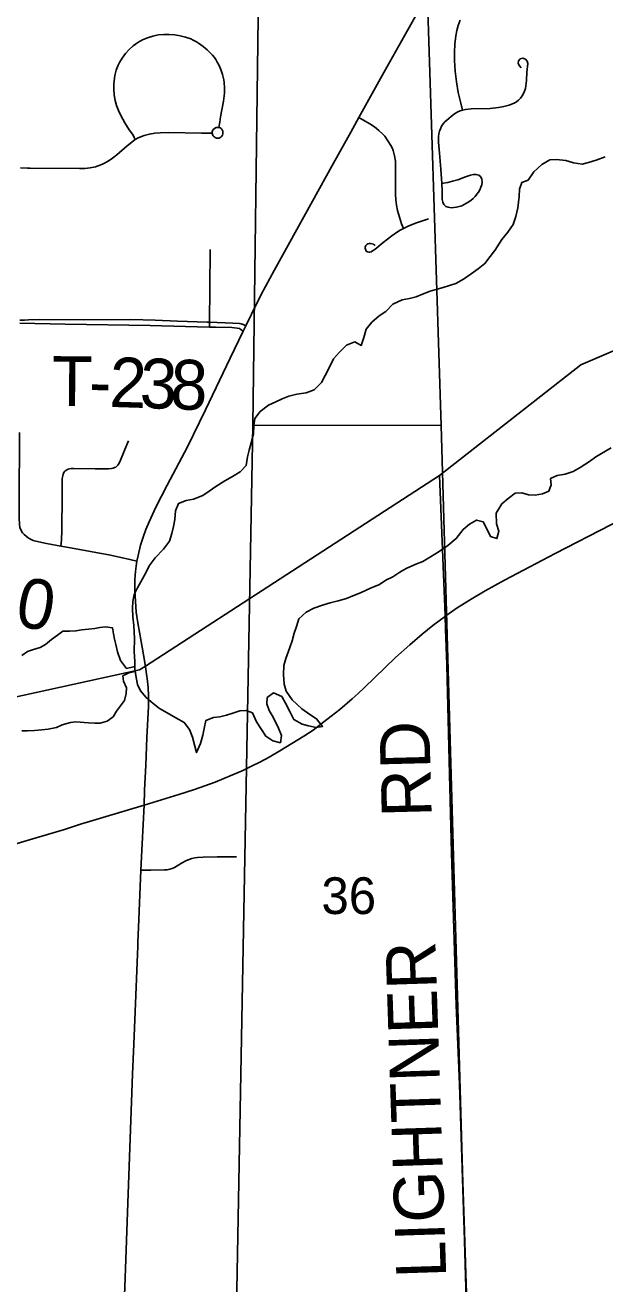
# Model space of a CAD drawing. Extents: x 63.4 to 97.4, y 0.4 to 22.4.
# Drawn here: x 67.452 to 68.112, y 16.594 to 18.029 of the extents above; entities that cross this region are included whole.
import ezdxf

# ---------------------------------------------------------------- set-up
doc = ezdxf.new("R2010")
doc.units = 0
for name, color, linetype in [('GM_X_County_Road', 7, 'Continuous'), ('GM_X_County_Road_Text', 7, 'Continuous'), ('GM_X_Minor_River', 7, 'Continuous'), ('GM_X_Section', 7, 'Continuous'), ('GM_X_Section_Text', 7, 'Continuous'), ('GM_X_State_Route', 7, 'Continuous'), ('GM_X_Township_Road', 7, 'Continuous'), ('GM_X_Township_Road_Text', 7, 'Continuous')]:
    doc.layers.add(name, color=color, linetype=linetype)

msp = doc.modelspace()

# ---------------------------------------------------------------- linework, layer by layer
at = {"layer": 'GM_X_County_Road'}
for points in [[(67.1507, 17.1994), (67.5821, 17.2942), (67.5887, 17.2982), (67.9238, 17.5156), (68.0846, 17.6418), (68.1482, 17.6693)], [(68.1482, 17.6693), (68.0846, 17.6418), (67.9238, 17.5156), (67.9301, 17.356), (67.9306, 17.3404), (67.9319, 17.3001), (67.9354, 17.1603), (67.9374, 17.0857), (67.9399, 16.9987), (67.9427, 16.9118), (67.9463, 16.8217), (67.9514, 16.6664), (67.954, 16.595), (67.9575, 16.4894)], [(67.4926, 17.4352), (67.4761, 17.4383), (67.4639, 17.4409), (67.4609, 17.4418), (67.4579, 17.4431), (67.4551, 17.4447), (67.4528, 17.4464), (67.4508, 17.4484), (67.4487, 17.4505), (67.4473, 17.453), (67.4459, 17.4564), (67.4454, 17.4601), (67.445, 17.4671), (67.4451, 17.4836), (67.4454, 17.5646)], [(67.9575, 16.4894), (67.954, 16.595), (67.9514, 16.6664), (67.9463, 16.8217), (67.9427, 16.9118), (67.9399, 16.9987), (67.9374, 17.0857), (67.9354, 17.1603), (67.9319, 17.3001), (67.9306, 17.3404), (67.9301, 17.356), (67.9238, 17.5156), (67.5887, 17.2982), (67.5821, 17.2942), (67.1507, 17.1994)], [(67.5791, 17.4182), (67.5712, 17.4201), (67.549, 17.425), (67.5035, 17.4332), (67.4926, 17.4352)]]:
    msp.add_lwpolyline(points, dxfattribs=at)
at = {"layer": 'GM_X_Minor_River'}
for points in [[(68.1122, 17.8789), (68.1019, 17.8751), (68.0932, 17.8724), (68.086, 17.8708), (68.0761, 17.8723), (68.0674, 17.8749), (68.0567, 17.876), (68.0492, 17.8756), (68.0401, 17.8702), (68.031, 17.8618), (68.0246, 17.8526), (68.0174, 17.8496), (68.0148, 17.842), (68.0144, 17.834), (68.013, 17.821)], [(68.1122, 17.8789), (68.1019, 17.8751), (68.0932, 17.8724), (68.086, 17.8708), (68.0761, 17.8723), (68.0674, 17.8749), (68.0567, 17.876), (68.0492, 17.8756), (68.0401, 17.8702), (68.031, 17.8618), (68.0246, 17.8526), (68.0174, 17.8496), (68.0148, 17.842), (68.0144, 17.834), (68.013, 17.821)], [(68.013, 17.821), (68.0104, 17.8111), (68.0074, 17.802), (68.0014, 17.7932), (67.9946, 17.7848), (67.9867, 17.7723), (67.9862, 17.7718)], [(67.9862, 17.7718), (67.9753, 17.7574), (67.9678, 17.7513), (67.9598, 17.7455), (67.9508, 17.7394), (67.9424, 17.7348), (67.928, 17.7302), (67.9208, 17.7282), (67.9129, 17.7259), (67.9041, 17.7225), (67.8969, 17.7194), (67.8894, 17.7175), (67.881, 17.7159), (67.8704, 17.7109), (67.8625, 17.7029), (67.8549, 17.6979), (67.8466, 17.6906), (67.8402, 17.6826), (67.8376, 17.6731), (67.8346, 17.664), (67.8273, 17.6681), (67.8179, 17.6643), (67.8099, 17.6563), (67.8031, 17.6486), (67.7986, 17.6399), (67.7934, 17.6296), (67.7892, 17.6216), (67.7809, 17.6136), (67.7718, 17.6101), (67.7612, 17.6085), (67.7521, 17.6062), (67.7445, 17.6031), (67.7373, 17.5997), (67.729, 17.5958), (67.7195, 17.5889), (67.7135, 17.5806), (67.7124, 17.5729), (67.7117, 17.5631), (67.7091, 17.5528), (67.7069, 17.5448), (67.705, 17.5372), (67.7035, 17.5273), (67.6967, 17.52), (67.688, 17.5147), (67.6793, 17.5097), (67.6691, 17.5032), (67.6615, 17.4978), (67.654, 17.4929), (67.6437, 17.4886), (67.635, 17.4871), (67.6263, 17.484), (67.6229, 17.4756), (67.6222, 17.4657), (67.6207, 17.4577), (67.6189, 17.4497), (67.6163, 17.441), (67.6095, 17.4318), (67.6, 17.4219), (67.5932, 17.4128), (67.5895, 17.4055), (67.5853, 17.3979), (67.5797, 17.3876), (67.5759, 17.38), (67.5745, 17.372), (67.5741, 17.364), (67.5746, 17.3545), (67.5754, 17.3446), (67.5758, 17.3374), (67.5762, 17.3294), (67.5759, 17.315), (67.5767, 17.3036), (67.5767, 17.2979)], [(67.981, 17.765), (67.9753, 17.7574), (67.9678, 17.7513), (67.9598, 17.7455), (67.9508, 17.7394), (67.9424, 17.7348), (67.928, 17.7302), (67.9208, 17.7282), (67.9129, 17.7259), (67.9041, 17.7225), (67.8969, 17.7194), (67.8894, 17.7175), (67.881, 17.7159), (67.8704, 17.7109), (67.8625, 17.7029), (67.8549, 17.6979), (67.8466, 17.6906), (67.8402, 17.6826), (67.8376, 17.6731), (67.8346, 17.664), (67.8273, 17.6681), (67.8179, 17.6643), (67.8099, 17.6563), (67.8031, 17.6486), (67.7986, 17.6399), (67.7934, 17.6296), (67.7892, 17.6216), (67.7809, 17.6136), (67.7718, 17.6101), (67.7612, 17.6085), (67.7521, 17.6062), (67.7445, 17.6031), (67.7373, 17.5997), (67.729, 17.5958), (67.7195, 17.5889), (67.7135, 17.5806), (67.7124, 17.5729), (67.7117, 17.5631), (67.7091, 17.5528), (67.7069, 17.5448), (67.705, 17.5372), (67.7035, 17.5273), (67.6967, 17.52), (67.688, 17.5147), (67.6793, 17.5097), (67.6691, 17.5032), (67.6615, 17.4978), (67.654, 17.4929), (67.6437, 17.4886), (67.635, 17.4871), (67.6263, 17.484), (67.6229, 17.4756), (67.6222, 17.4657), (67.6207, 17.4577), (67.6189, 17.4497), (67.6163, 17.441), (67.6095, 17.4318), (67.6, 17.4219), (67.5932, 17.4128), (67.5895, 17.4055), (67.5853, 17.3979), (67.5797, 17.3876), (67.5759, 17.38), (67.5745, 17.372), (67.5741, 17.364), (67.5746, 17.3545), (67.5754, 17.3446), (67.5758, 17.3374), (67.5762, 17.3294), (67.5759, 17.315), (67.5767, 17.3036), (67.5768, 17.2952), (67.5783, 17.2854), (67.5799, 17.2774), (67.583, 17.2702), (67.5898, 17.2626), (67.5975, 17.2558), (67.6047, 17.2501), (67.6135, 17.2452), (67.6234, 17.2396), (67.6329, 17.2343), (67.639, 17.2263), (67.6425, 17.2176), (67.6452, 17.207), (67.6471, 17.1998), (67.6516, 17.2101), (67.6542, 17.2196), (67.6557, 17.2272), (67.6575, 17.2363), (67.6663, 17.2398), (67.6735, 17.2406), (67.6811, 17.2425), (67.6883, 17.2448), (67.6962, 17.2475), (67.7034, 17.2479), (67.7107, 17.2453), (67.7153, 17.2351), (67.721, 17.226), (67.726, 17.2184), (67.734, 17.2131), (67.7427, 17.2109)], [(67.7427, 17.2109), (67.7438, 17.2192), (67.7404, 17.2276), (67.7342, 17.2401), (67.7296, 17.248), (67.7269, 17.2553), (67.7273, 17.2625), (67.7348, 17.2678), (67.744, 17.2637), (67.7482, 17.2561), (67.7536, 17.2459), (67.7578, 17.2375), (67.7673, 17.2323), (67.7745, 17.2304), (67.7833, 17.2285), (67.7905, 17.2297), (67.7836, 17.2384), (67.776, 17.2433), (67.7668, 17.2497), (67.7558, 17.26), (67.7489, 17.2698), (67.7466, 17.2778), (67.7461, 17.2888), (67.7465, 17.2991), (67.7487, 17.3071), (67.7532, 17.3196), (67.7558, 17.3272), (67.758, 17.336), (67.7607, 17.3436), (67.7636, 17.3524), (67.772, 17.36), (67.7807, 17.3646), (67.7905, 17.3681), (67.7992, 17.3704), (67.8083, 17.3727), (67.8178, 17.3754), (67.825, 17.3785), (67.8337, 17.3819), (67.8451, 17.3873), (67.8553, 17.3916), (67.8625, 17.3965), (67.8705, 17.4004), (67.8784, 17.4057), (67.8856, 17.4099), (67.8966, 17.4146), (67.9046, 17.4176), (67.9133, 17.423), (67.9231, 17.4291), (67.9333, 17.436), (67.9428, 17.444), (67.9507, 17.4543), (67.9579, 17.4604), (67.9658, 17.465), (67.9734, 17.4628), (67.9784, 17.4533), (67.9819, 17.4461), (67.9891, 17.4439), (67.9913, 17.4522), (67.9886, 17.4606), (67.9882, 17.4728), (67.9946, 17.4834), (68.0018, 17.4895), (68.0097, 17.4957), (68.0173, 17.4961), (68.0249, 17.4938), (68.0325, 17.4935), (68.0408, 17.4947), (68.048, 17.4977), (68.0507, 17.505), (68.0502, 17.5122), (68.0578, 17.5156), (68.0669, 17.5172), (68.076, 17.5203), (68.084, 17.5249), (68.0946, 17.5318), (68.1018, 17.5371), (68.1192, 17.5471)], [(67.5767, 17.2979), (67.5737, 17.2971), (67.5673, 17.2959), (67.5604, 17.3047), (67.5569, 17.3149), (67.555, 17.3229), (67.5534, 17.3293), (67.5526, 17.3354), (67.5511, 17.3422), (67.5435, 17.3433), (67.537, 17.3426), (67.531, 17.3414), (67.5238, 17.3406), (67.5162, 17.3398), (67.5097, 17.3386), (67.5025, 17.3382), (67.4949, 17.3382), (67.4885, 17.3336), (67.482, 17.3286), (67.4749, 17.3229), (67.4688, 17.3198), (67.4612, 17.3175), (67.4544, 17.3152), (67.448, 17.3106)], [(67.4545, 17.2247), (67.4625, 17.2251), (67.4708, 17.2259), (67.478, 17.2267), (67.4875, 17.2283), (67.4939, 17.2314), (67.5034, 17.2341), (67.5095, 17.2349), (67.5239, 17.2338), (67.5311, 17.2334), (67.5372, 17.2335), (67.5452, 17.2358), (67.552, 17.2408), (67.5557, 17.2469), (67.5603, 17.253), (67.5648, 17.2591), (67.567, 17.2671), (67.5674, 17.2735), (67.5639, 17.2811), (67.5631, 17.2872), (67.5699, 17.2906), (67.5772, 17.2923)], [(67.4545, 17.2247), (67.4625, 17.2251), (67.4708, 17.2259), (67.478, 17.2267), (67.4875, 17.2283), (67.4939, 17.2314), (67.5034, 17.2341), (67.5095, 17.2349), (67.5239, 17.2338), (67.5311, 17.2334), (67.5372, 17.2335), (67.5452, 17.2358), (67.552, 17.2408), (67.5557, 17.2469), (67.5603, 17.253), (67.5648, 17.2591), (67.567, 17.2671), (67.5674, 17.2735), (67.5639, 17.2811), (67.5631, 17.2872), (67.5699, 17.2906), (67.5772, 17.2923)], [(67.5772, 17.2923), (67.5783, 17.2854), (67.5799, 17.2774), (67.583, 17.2702), (67.5898, 17.2626), (67.5975, 17.2558), (67.6047, 17.2501), (67.6135, 17.2452), (67.6234, 17.2396), (67.6329, 17.2343), (67.639, 17.2263), (67.6425, 17.2176), (67.6452, 17.207), (67.6471, 17.1998), (67.6516, 17.2101), (67.6542, 17.2196), (67.6557, 17.2272), (67.6575, 17.2363), (67.6663, 17.2398), (67.6735, 17.2406), (67.6811, 17.2425), (67.6883, 17.2448), (67.6962, 17.2475), (67.7034, 17.2479), (67.7107, 17.2453), (67.7153, 17.2351), (67.721, 17.226), (67.726, 17.2184), (67.734, 17.2131), (67.7427, 17.2109)], [(67.448, 17.2247), (67.4545, 17.2247)]]:
    msp.add_lwpolyline(points, dxfattribs=at)
at = {"layer": 'GM_X_Section'}
for points in [[(67.8938, 18.5672), (67.9257, 17.5727), (67.711, 17.573), (67.7239, 18.5617)], [(67.9257, 17.5727), (67.9544, 16.5634), (67.725, 16.5661), (67.6925, 16.5663), (67.711, 17.573)]]:
    msp.add_lwpolyline(points, close=True, dxfattribs=at)
at = {"layer": 'GM_X_State_Route'}
msp.add_line((67.5918, 17.2741), (67.5908, 17.2844), dxfattribs=at)
for points in [[(67.5791, 17.4182), (67.5804, 17.4247), (67.5832, 17.4364), (67.5862, 17.4456), (67.5893, 17.4543), (67.5929, 17.4628), (67.6008, 17.4797), (67.6134, 17.5046), (67.6367, 17.5486), (67.6571, 17.5905), (67.6852, 17.6494), (67.7001, 17.6803), (67.7031, 17.6864), (67.7095, 17.6998), (67.7206, 17.722), (67.7352, 17.7494), (67.8028, 17.8718), (67.8226, 17.907), (67.8319, 17.9239), (67.8601, 17.9751), (67.8874, 18.0239), (67.921, 18.0834)], [(67.9304, 17.3555), (67.931, 17.3559), (67.9438, 17.3648), (67.9596, 17.3748), (67.9756, 17.3843), (67.9975, 17.3963), (68.0552, 17.4268), (68.1186, 17.4596), (68.1741, 17.4875), (68.2104, 17.5053), (68.2357, 17.5172), (68.2529, 17.5246), (68.2703, 17.5314), (68.2879, 17.5375), (68.3058, 17.543), (68.3238, 17.5479), (68.3481, 17.5534), (68.3873, 17.5614), (68.4247, 17.5688), (68.4628, 17.5762), (68.5492, 17.5935), (68.7289, 17.6295), (68.7898, 17.6417), (68.8027, 17.6443)], [(67.5908, 17.2844), (67.5905, 17.2865), (67.5889, 17.2977), (67.5878, 17.305), (67.584, 17.3264), (67.5801, 17.3478), (67.5784, 17.3601), (67.5773, 17.3724), (67.5768, 17.3848), (67.5769, 17.3972), (67.5774, 17.4064), (67.5786, 17.4156), (67.5791, 17.4182)], [(67.831, 17.2674), (67.8379, 17.2737), (67.8737, 17.3081), (67.8898, 17.3228), (67.9039, 17.335), (67.916, 17.3447), (67.9304, 17.3555)], [(67.5872, 17.14), (67.5878, 17.1572), (67.5892, 17.1856), (67.5903, 17.2172), (67.5923, 17.2523), (67.5923, 17.2647), (67.5918, 17.2741)], [(67.5872, 17.14), (67.6269, 17.1519), (67.6446, 17.1576), (67.6683, 17.166), (67.6852, 17.1732), (67.6988, 17.1791), (67.7104, 17.1846), (67.719, 17.1889), (67.7296, 17.1947), (67.7419, 17.2019), (67.769, 17.2185), (67.7796, 17.2256), (67.7955, 17.2374), (67.81, 17.249), (67.8242, 17.2611), (67.831, 17.2674)], [(67.4326, 17.0931), (67.4642, 17.1026), (67.4965, 17.1123), (67.5148, 17.1181), (67.5872, 17.14)], [(67.5803, 16.984), (67.5808, 17.0006), (67.5837, 17.0659), (67.5851, 17.096), (67.5872, 17.14)], [(67.555, 16.4107), (67.5582, 16.4541), (67.5625, 16.5224), (67.5653, 16.5907), (67.5665, 16.6218), (67.568, 16.6653), (67.574, 16.8332), (67.5756, 16.8673), (67.5777, 16.9233), (67.5801, 16.9792), (67.5803, 16.984)]]:
    msp.add_lwpolyline(points, dxfattribs=at)
at = {"layer": 'GM_X_Township_Road'}
for points in [[(67.9497, 17.9322), (67.9478, 17.9401), (67.945, 17.9522), (67.9429, 17.9644), (67.9415, 17.9767), (67.9407, 17.989), (67.9406, 17.9983), (67.941, 18.0076), (67.9422, 18.0168), (67.9433, 18.0229), (67.9449, 18.0288), (67.9471, 18.0347)], [(67.5771, 17.8989), (67.5761, 17.9012), (67.5752, 17.903), (67.5742, 17.9047), (67.5702, 17.9099), (67.5652, 17.9178), (67.5607, 17.926), (67.5581, 17.9318), (67.556, 17.9377), (67.5543, 17.9433), (67.5533, 17.9499), (67.5528, 17.9561), (67.5527, 17.9624), (67.5534, 17.9686), (67.5539, 17.9717), (67.5556, 17.9777), (67.5578, 17.9836), (67.5592, 17.9864), (67.5624, 17.9917), (67.5662, 17.9967), (67.5704, 18.0014), (67.575, 18.0057), (67.5775, 18.0076), (67.5801, 18.0093), (67.5856, 18.0123), (67.5913, 18.0148), (67.5973, 18.0167), (67.6034, 18.018), (67.6096, 18.0186), (67.6159, 18.0186), (67.6221, 18.0181), (67.6283, 18.0171), (67.6344, 18.0155), (67.6403, 18.0134), (67.643, 18.0121), (67.6468, 18.0101), (67.6494, 18.0086), (67.6544, 18.005), (67.659, 18.001), (67.665, 17.9948), (67.6673, 17.9921), (67.6689, 17.9899), (67.6706, 17.9869), (67.6725, 17.9839), (67.6748, 17.9787), (67.6767, 17.9729), (67.6782, 17.967), (67.6786, 17.9639), (67.679, 17.9578), (67.6788, 17.9517), (67.6776, 17.9426), (67.6742, 17.9245), (67.6734, 17.9184), (67.6725, 17.9124)], [(67.9497, 17.9322), (67.9503, 17.9324), (67.9534, 17.933), (67.9596, 17.9336), (67.9814, 17.9343), (67.9907, 17.9352), (67.9968, 17.9363), (68.0029, 17.9378), (68.0058, 17.9389), (68.0086, 17.9402), (68.0113, 17.9418), (68.0137, 17.9437), (68.0159, 17.9459), (68.0178, 17.9484), (68.0193, 17.9511), (68.0205, 17.954), (68.0214, 17.957), (68.022, 17.96), (68.0228, 17.9662), (68.0231, 17.9756), (68.0234, 17.9788), (68.024, 17.9822), (68.0241, 17.9853), (68.0234, 17.9881), (68.0215, 17.9904), (68.0186, 17.9914), (68.0156, 17.9908), (68.0136, 17.9886), (68.0133, 17.9855), (68.0146, 17.9827), (68.0168, 17.9805)], [(67.8825, 17.7974), (67.8804, 17.8027), (67.8769, 17.8141), (67.8758, 17.818), (67.8747, 17.8238), (67.874, 17.8301), (67.8735, 17.8363), (67.8734, 17.8457), (67.8737, 17.8677), (67.8734, 17.874), (67.8723, 17.8802), (67.8707, 17.8863), (67.8696, 17.8892), (67.8682, 17.8921), (67.865, 17.8974), (67.8613, 17.9025), (67.8592, 17.9048), (67.8547, 17.9092), (67.8498, 17.9131), (67.8445, 17.9166), (67.8391, 17.9197), (67.8319, 17.9239)], [(67.9262, 17.8488), (67.9251, 17.8648), (67.9238, 17.8834), (67.9226, 17.8958), (67.9225, 17.9021), (67.9228, 17.9052), (67.9235, 17.9082), (67.9246, 17.9111), (67.926, 17.9139), (67.9278, 17.9165), (67.9297, 17.9188), (67.932, 17.921), (67.9392, 17.927), (67.9418, 17.9287), (67.9445, 17.9303), (67.9473, 17.9315), (67.9497, 17.9322)], [(67.6648, 17.9061), (67.6648, 17.9074), (67.6651, 17.9086), (67.6657, 17.9098), (67.667, 17.9111), (67.6684, 17.912), (67.6694, 17.9124), (67.6703, 17.9125), (67.6713, 17.9125), (67.6725, 17.9124)], [(67.6725, 17.9124), (67.6737, 17.9121), (67.675, 17.9113), (67.6757, 17.9107), (67.6763, 17.9098), (67.6769, 17.9084), (67.6771, 17.9069), (67.677, 17.9052), (67.6765, 17.9036), (67.6758, 17.9025), (67.6751, 17.9017), (67.6746, 17.9013), (67.6738, 17.9009), (67.6729, 17.9005), (67.6714, 17.9003), (67.6698, 17.9005), (67.6682, 17.9011), (67.6669, 17.902), (67.6658, 17.9031), (67.6653, 17.9041), (67.665, 17.9052), (67.6648, 17.9061)], [(67.4466, 17.8665), (67.4545, 17.8663), (67.4576, 17.8663), (67.5136, 17.8656), (67.5198, 17.8658), (67.526, 17.8665), (67.5321, 17.8678), (67.5379, 17.8698), (67.5408, 17.8711), (67.5462, 17.8741), (67.5514, 17.8776), (67.5563, 17.8814), (67.568, 17.8916), (67.5771, 17.8989)], [(67.5771, 17.8989), (67.5806, 17.9007), (67.5853, 17.9027), (67.5873, 17.9034), (67.5934, 17.905), (67.5995, 17.906), (67.6057, 17.9065), (67.615, 17.9067), (67.6525, 17.9059), (67.6587, 17.906), (67.6648, 17.9061)], [(67.9262, 17.8488), (67.9282, 17.8491), (67.9331, 17.8499), (67.9385, 17.8512), (67.9445, 17.8529), (67.9533, 17.8561), (67.9591, 17.8583), (67.9622, 17.859), (67.9653, 17.859), (67.9683, 17.8583), (67.9706, 17.8562), (67.9719, 17.8534), (67.9723, 17.8504), (67.9719, 17.8473), (67.9709, 17.8443), (67.9696, 17.8415), (67.968, 17.8388), (67.9662, 17.8363), (67.9642, 17.8339), (67.962, 17.8317), (67.9597, 17.8296), (67.9572, 17.8277), (67.9545, 17.8261), (67.9518, 17.8246), (67.949, 17.8233), (67.946, 17.8223), (67.943, 17.8215), (67.9399, 17.8211), (67.9368, 17.821), (67.9337, 17.8215), (67.9308, 17.8225), (67.9286, 17.8246), (67.9273, 17.8274), (67.9268, 17.8305), (67.9265, 17.8399), (67.9262, 17.8488)], [(67.8825, 17.7974), (67.8878, 17.7999), (67.8964, 17.8034), (67.9031, 17.8057), (67.9112, 17.8082)], [(67.8503, 17.778), (67.8494, 17.7789), (67.8486, 17.7793), (67.8468, 17.7799), (67.8451, 17.7802), (67.8437, 17.7801), (67.8421, 17.7798), (67.8413, 17.7795), (67.8404, 17.7788), (67.8397, 17.778), (67.8394, 17.7773), (67.8391, 17.7762), (67.839, 17.775), (67.8393, 17.7737), (67.8396, 17.7726), (67.8402, 17.7716), (67.841, 17.771), (67.8418, 17.7706), (67.8431, 17.7704), (67.8438, 17.7703), (67.8445, 17.7704), (67.8459, 17.7709), (67.8473, 17.7717), (67.8499, 17.7735), (67.8595, 17.7814), (67.8692, 17.789), (67.8758, 17.7936), (67.879, 17.7955), (67.8825, 17.7974)], [(67.6618, 17.6904), (67.6621, 17.7295), (67.6626, 17.7735)], [(67.4456, 17.6927), (67.451, 17.693), (67.4558, 17.6933), (67.4679, 17.6935), (67.5187, 17.6932), (67.5723, 17.6936), (67.5999, 17.6928), (67.6252, 17.6916), (67.6589, 17.6905), (67.6618, 17.6904), (67.6882, 17.6895), (67.6958, 17.689), (67.6978, 17.6887), (67.7, 17.6879), (67.7031, 17.6864)], [(67.4456, 17.6895), (67.4975, 17.6883), (67.594, 17.6867), (67.6344, 17.6858), (67.6618, 17.685)], [(67.6618, 17.685), (67.6618, 17.6878), (67.6618, 17.6904)], [(67.6618, 17.685), (67.6687, 17.6848), (67.6873, 17.6846), (67.6932, 17.6839), (67.6959, 17.6832), (67.6978, 17.682), (67.7001, 17.6803)], [(67.4926, 17.4352), (67.4929, 17.4385), (67.4932, 17.442), (67.4935, 17.4532), (67.494, 17.4936), (67.4939, 17.5063), (67.4939, 17.51), (67.494, 17.5125), (67.4946, 17.5155), (67.4951, 17.5173), (67.496, 17.5192), (67.4969, 17.5205), (67.498, 17.5215), (67.4993, 17.5222), (67.5009, 17.5229), (67.5022, 17.5232), (67.5042, 17.5236), (67.507, 17.5239), (67.5317, 17.5232), (67.541, 17.5233), (67.5468, 17.5235), (67.5501, 17.5238), (67.552, 17.5241), (67.5536, 17.5247), (67.555, 17.5254), (67.5564, 17.5265), (67.5572, 17.5274), (67.5581, 17.5288), (67.5597, 17.5314), (67.5655, 17.5454), (67.5694, 17.5553)], [(67.9724, 16.0591), (67.97, 16.1534), (67.9685, 16.2062), (67.9655, 16.2776), (67.9639, 16.3211), (67.9591, 16.4484), (67.9577, 16.4888), (67.9542, 16.5944), (67.9516, 16.6658), (67.9465, 16.8211), (67.9429, 16.9112), (67.9401, 16.9982), (67.9376, 17.0851), (67.9356, 17.1597), (67.9321, 17.2995), (67.9309, 17.3399), (67.9304, 17.3555)], [(67.5837, 17.0659), (67.5949, 17.066), (67.6106, 17.0661), (67.6136, 17.0663), (67.6164, 17.0668), (67.6192, 17.0676), (67.6217, 17.0689), (67.6297, 17.0739), (67.6355, 17.0768), (67.6385, 17.078), (67.6417, 17.079), (67.6449, 17.0798), (67.6481, 17.0803), (67.6545, 17.0808), (67.6703, 17.0809), (67.6923, 17.081)]]:
    msp.add_lwpolyline(points, dxfattribs=at)

# ---------------------------------------------------------------- texts
at = {"layer": 'GM_X_County_Road_Text'}
msp.add_text('0', height=0.0568, rotation=350.2727, dxfattribs=at).set_placement((67.4388, 17.3448))
at = {"layer": 'GM_X_Section_Text'}
msp.add_text('36', height=0.04186, rotation=0, dxfattribs=at).set_placement((67.7892, 17.0158))
at = {"layer": 'GM_X_Township_Road_Text'}
for s, height, rotation, p in [('T', 0.0568, 359.3987, (67.4819, 17.5951)), ('2', 0.0568, 358.143, (67.5471, 17.594)), ('3', 0.0568, 357.9669, (67.5817, 17.5929)), ('8', 0.0568, 357.9074, (67.6164, 17.5916)), ('-', 0.0568, 358.4768, (67.524, 17.5946)), ('RD', 0.05682, 91.4806, (67.9148, 17.1268)), ('LIGHTNER', 0.05682, 91.8766, (67.9314, 16.6016))]:
    msp.add_text(s, height=height, rotation=rotation, dxfattribs=at).set_placement(p)

doc.saveas('drawing.dxf')
